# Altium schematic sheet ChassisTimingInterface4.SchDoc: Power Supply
size B; DocumentNumber: 5; Revision: C; SheetNumber: 4; SheetTotal: 12
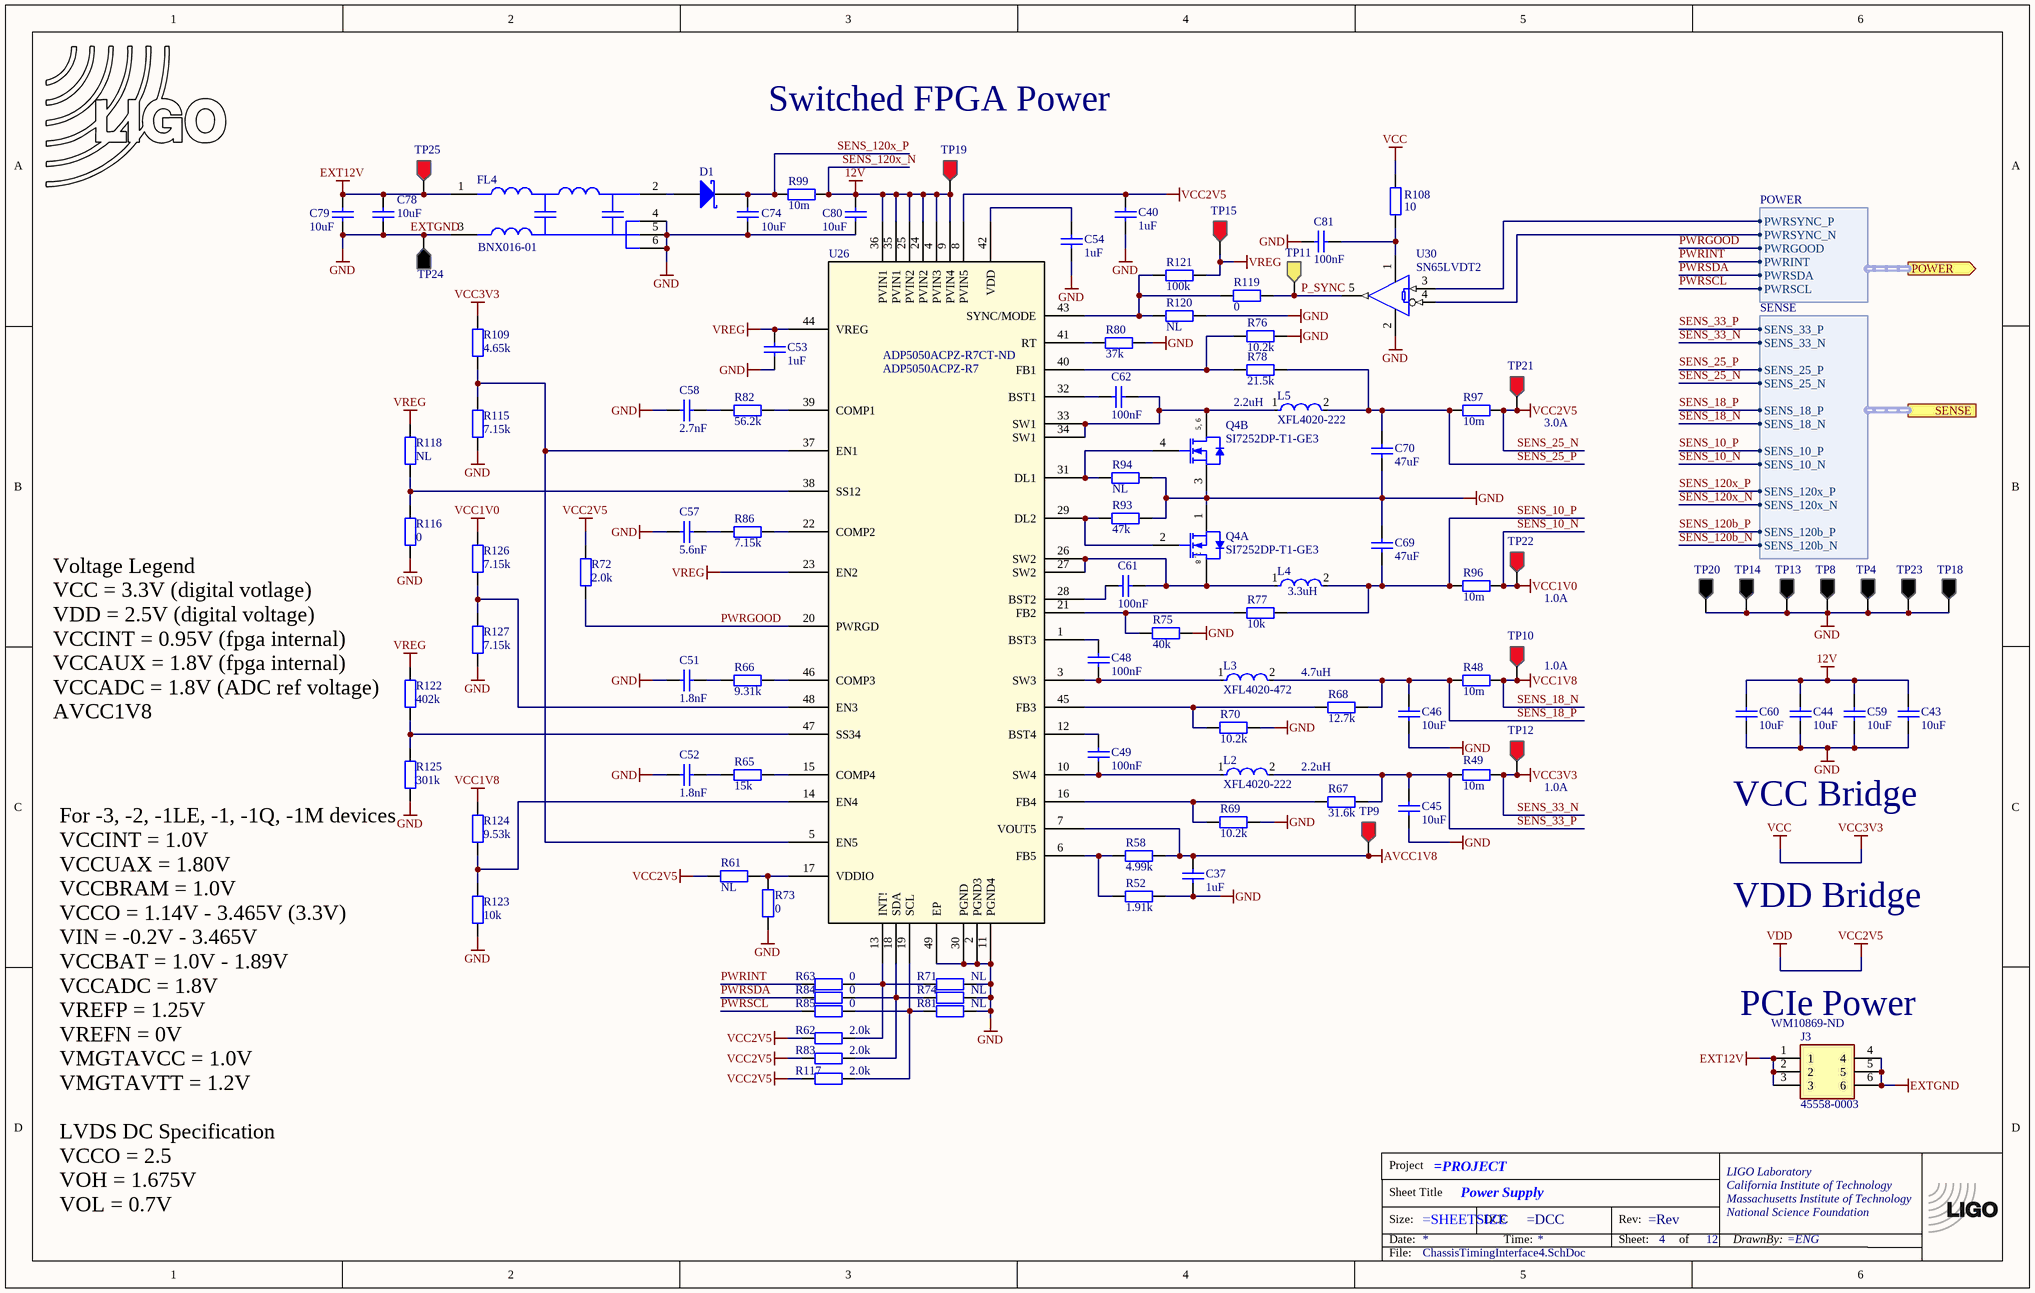
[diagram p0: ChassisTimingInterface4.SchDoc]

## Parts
*  TitleBlock  (value not drawn)  (graphical)
C37  value 1uF  [CC1005-0402]  (hidden comment: 1.0u)
C40  value 1uF  [CC1005-0402]  (hidden comment: 1.0u)
C43  10uF  [CC2013-0805]
C44  10uF  [CC2013-0805]
C45  10uF  [CC2013-0805]
C46  10uF  [CC2013-0805]
C48  100nF  [CC1005-0402]
C49  100nF  [CC1005-0402]
C51  1.8nF  [CC1005-0402]
C52  1.8nF  [CC1005-0402]
C53  value 1uF  [CC1005-0402]  (hidden comment: 1.0u)
C54  value 1uF  [CC1005-0402]  (hidden comment: 1.0u)
C57  5.6nF  [CC1005-0402]
C58  2.7nF  [CC1005-0402]
C59  10uF  [CC2013-0805]
C60  10uF  [CC2013-0805]
C61  100nF  [CC1005-0402]
C62  100nF  [CC1005-0402]
C69  47uF  [CC3216-1206]
C70  47uF  [CC3216-1206]
C74  10uF  [CC2013-0805]
C78  10uF  [CC2013-0805]
C79  10uF  [CC2013-0805]
C80  10uF  [CC2013-0805]
C81  100nF  [CC1005-0402]
D1  LSM115JE3/TR13  [MCSM-DO-214BA-2_L]  (value not drawn)
FL4  BNX016-01  [MURA-BNX016-01_V]
J3  45558-0003  Supplier Part Number 1: WM10869-ND  [455580003]
L2  XFL4020-222  [FP-XAL40-MFG]
L3  XFL4020-472  [FP-XAL40-MFG]
L4  XFL4020-332  [FP-XAL40-MFG]  (value not drawn)
L5  XFL4020-222  [FP-XAL40-MFG]
LOGO4  LIGO logo  [LIGO_LOGO]  (value not drawn)  (graphical)
Q4  SI7252DP-T1-GE3  [VISH-POWERPAKSO-8_A_V]  (parts A,B of 2)
R48  10m  [CC3216-1206]
R49  10m  [CC3216-1206]
R52  1.91k  [CR1005-0402]
R58  4.99k  [CR1608-0603]
R61  NL  [CR1005-0402]
R62  2.0k  [CR1005-0402]
R63  0  [CR1005-0402]
R65  15k  [CR1005-0402]
R66  9.31k  [CR1005-0402]
R67  31.6k  [CR1005-0402]
R68  12.7k  [CR1005-0402]
R69  value 10.2k  [CR1005-0402]  (hidden comment: 10k)
R70  value 10.2k  [CR1005-0402]  (hidden comment: 10k)
R71  NL  [CR1005-0402]
R72  2.0k  [CR1005-0402]
R73  0  [CR1005-0402]
R74  NL  [CR1005-0402]
R75  value 40k  [CR1005-0402]  (hidden comment: 40.2k)
R76  value 10.2k  [CR1005-0402]  (hidden comment: 10k)
R77  10k  [CR1005-0402]
R78  21.5k  [CR1005-0402]
R80  value 37k  [CR1005-0402]  (hidden comment: 37.4k)
R81  NL  [CR1005-0402]
R82  56.2k  [CR1005-0402]
R83  2.0k  [CR1005-0402]
R84  0  [CR1005-0402]
R85  0  [CR1005-0402]
R86  7.15k  [CR1005-0402]
R93  47k  [CR1005-0402]
R94  NL  [CR1005-0402]
R96  10m  [CC3216-1206]
R97  10m  [CC3216-1206]
R99  10m  [CC3216-1206]
R108  value 10  [CR1005-0402]  (hidden comment: 10.0)
R109  value 4.65k  [CR1005-0402]  (hidden comment: 4.7k)
R115  7.15k  [CR1005-0402]
R116  0  [CR1005-0402]
R117  2.0k  [CR1005-0402]
R118  NL  [CR1005-0402]
R119  0  [CR1005-0402]
R120  NL  [CR1005-0402]
R121  100k  [CR1005-0402]
R122  402k  [CR1005-0402]
R123  10k  [CR1005-0402]
R124  9.53k  [CR1005-0402]
R125  301k  [CR1005-0402]
R126  7.15k  [CR1005-0402]
R127  7.15k  [CR1005-0402]
TP4  Testpoint  [TP1-BLK]  (value not drawn)
TP8  Testpoint  [TP1-BLK]  (value not drawn)
TP9  Testpoint  [TP1-RED]  (value not drawn)
TP10  Testpoint  [TP1-RED]  (value not drawn)
TP11  Testpoint  [TP1-YLW]  (value not drawn)
TP12  Testpoint  [TP1-RED]  (value not drawn)
TP13  Testpoint  [TP1-BLK]  (value not drawn)
TP14  Testpoint  [TP1-BLK]  (value not drawn)
TP15  Testpoint  [TP1-RED]  (value not drawn)
TP18  Testpoint  [TP1-BLK]  (value not drawn)
TP19  Testpoint  [TP1-RED]  (value not drawn)
TP20  Testpoint  [TP1-BLK]  (value not drawn)
TP21  Testpoint  [TP1-RED]  (value not drawn)
TP22  Testpoint  [TP1-RED]  (value not drawn)
TP23  Testpoint  [TP1-BLK]  (value not drawn)
TP24  Testpoint  [TP1-BLK]  (value not drawn)
TP25  Testpoint  [TP1-RED]  (value not drawn)
U26  ADP5050ACPZ-R7  Supplier Part Number 1: ADP5050ACPZ-R7CT-ND  [CP-48-13_L]
U30  SN65LVDT2  [SO-G5/E2.4]

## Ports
POWER (out, harness POWER), SENSE (harness SENSE)

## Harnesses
POWER: PWRSYNC_N, PWRSYNC_P, PWRGOOD, PWRINT, PWRSDA, PWRSCL
SENSE: SENS_33_P, SENS_33_N, SENS_25_P, SENS_25_N, SENS_18_P, SENS_18_N, SENS_10_P, SENS_10_N, SENS_120x_P, SENS_120x_N, SENS_120b_P, SENS_120b_N

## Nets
AVCC1V8: C37.2 R58.2 TP9.1 U26.7(VOUT5)
EXT12V: C78.1 C79.1 FL4.1(B) J3.1 J3.2 J3.3 TP25.1
EXTGND: C37.1 C40.1 C43.2 C44.2 C45.1 C46.1 C51.1 C52.1 C53.2 C54.1 C57.1 C58.1 C59.2 C60.2 C69.2 C70.1 C74.2 C78.2 C79.2 C80.2 C81.2 FL4.3(PSG) FL4.4(CG) FL4.5(CG) FL4.6(CG) J3.4 J3.5 J3.6 Q4.1(S1) Q4.3(S2) R52.2 R69.2 R70.2 R71.2 R73.1 R74.2 R75.2 R76.2 R80.2 R81.2 R93.2 R94.2 R115.1 R116.1 R120.2 R123.1 R125.1 R127.1 TP4.1 TP8.1 TP13.1 TP14.1 TP18.1 TP20.1 TP23.1 TP24.1 U26.2(PGND3) U26.11(PGND4) U26.30(PGND) U26.49(EP) U30.2(GND)  [also labelled GND]
SENS_10_N: R96.2 R126.2 TP22.1 ; port SENSE.SENS_10_N  [also labelled VCC1V0]
SENS_18_N: R48.2 R124.2 TP10.1 ; port SENSE.SENS_18_N  [also labelled VCC1V8]
SENS_25_N: C40.2 R61.2 R62.1 R72.2 R83.1 R97.2 R117.1 TP21.1 U26.8(PVIN5) ; port SENSE.SENS_25_N  [also labelled VCC2V5, VDD]
SENS_33_N: R49.2 R108.2 R109.2 TP12.1 ; port SENSE.SENS_33_N  [also labelled VCC, VCC3V3]
SENS_120x_N: C43.1 C44.1 C59.1 C60.1 C80.1 R99.2 TP19.1 U26.4(PVIN3) U26.9(PVIN4) U26.24(PVIN2) U26.25(PVIN2) U26.35(PVIN1) U26.36(PVIN1) ; port SENSE.SENS_120x_N  [also labelled 12V]
VREG: C53.1 R118.2 R121.2 R122.2 TP15.1 U26.23(EN2) U26.44(VREG)
P_SYNC: R119.2 TP11.1 U30.5(R)
PWRGOOD: R72.1 U26.20(PWRGD) ; port POWER.PWRGOOD
PWRINT: R63.1 ; port POWER.PWRINT
PWRSCL: R85.1 ; port POWER.PWRSCL
PWRSDA: R84.1 ; port POWER.PWRSDA
SENS_10_P: C69.1 L4.2 R77.2 R96.1 ; port SENSE.SENS_10_P
SENS_18_P: C46.2 L3.2 R48.1 R68.2 ; port SENSE.SENS_18_P
SENS_25_P: C70.2 L5.2 R78.2 R97.1 ; port SENSE.SENS_25_P
SENS_33_P: C45.2 L2.2 R49.1 R67.2 ; port SENSE.SENS_33_P
SENS_120x_P: C74.1 D1.2(K) R99.1 ; port SENSE.SENS_120x_P
NetC48_1: C48.1 L3.1 U26.3(SW3)
NetC48_2: C48.2 U26.1(BST3)
NetC49_1: C49.1 L2.1 U26.10(SW4)
NetC49_2: C49.2 U26.12(BST4)
NetC51_2: C51.2 R66.1
NetC52_2: C52.2 R65.1
NetC54_2: C54.2 U26.42(VDD)
NetC57_2: C57.2 R86.1
NetC58_2: C58.2 R82.1
NetC61_1: C61.1 U26.28(BST2)
NetC61_2: C61.2 L4.1 Q4.7(D1) Q4.8(D1) U26.26(SW2) U26.27(SW2)
NetC62_1: C62.1 U26.32(BST1)
NetC62_2: C62.2 L5.1 Q4.5(D2) Q4.6(D2) U26.33(SW1) U26.34(SW1)
NetC81_1: C81.1 R108.1 U30.1(VCC)
NetD1_1: D1.1(A) FL4.2(CB)
NetQ4_2: Q4.2(G1) R93.1 U26.29(DL2)
NetQ4_4: Q4.4(G2) R94.1 U26.31(DL1)
NetR52_1: R52.1 R58.1 U26.6(FB5)
NetR61_1: R61.1 R73.2 U26.17(VDDIO)
NetR62_2: R62.2 R63.2 R71.1 U26.13(INT!)
NetR65_2: R65.2 U26.15(COMP4)
NetR66_2: R66.2 U26.46(COMP3)
NetR67_1: R67.1 R69.1 U26.16(FB4)
NetR68_1: R68.1 R70.1 U26.45(FB3)
NetR74_1: R74.1 R83.2 R84.2 U26.18(SDA)
NetR75_1: R75.1 R77.1 U26.21(FB2)
NetR76_1: R76.1 R78.1 U26.40(FB1)
NetR80_1: R80.1 U26.41(RT)
NetR81_1: R81.1 R85.2 R117.2 U26.19(SCL)
NetR82_2: R82.2 U26.39(COMP1)
NetR86_2: R86.2 U26.22(COMP2)
NetR109_1: R109.1 R115.2 U26.5(EN5) U26.37(EN1)
NetR116_2: R116.2 R118.1 U26.38(SS12)
NetR119_1: R119.1 R120.1 R121.1 U26.43(SYNC/MODE)
NetR122_1: R122.1 R125.2 U26.47(SS34)
NetR123_2: R123.2 R124.1 U26.14(EN4)
NetR126_1: R126.1 R127.2 U26.48(EN3)
NetU30_3: U30.3(A) ; port POWER.PWRSYNC_P
NetU30_4: U30.4(B) ; port POWER.PWRSYNC_N

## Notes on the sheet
- Switched FPGA Power
- 2.2uH
- 3.0A
- (near L4) 3.3uH
- 1.0A
- 4.7uH
- (near TP10) 1.0A
- Voltage Legend
  VCC = 3.3V (digital votlage)
  VDD = 2.5V (digital voltage)
  VCCINT = 0.95V (fpga internal)
  VCCAUX = 1.8V (fpga internal)
  VCCADC = 1.8V (ADC ref voltage)
  AVCC1V8
- VCC Bridge
- VDD Bridge
- (near J3) PCIe Power
- (near R125) For -3, -2, -1LE, -1, -1Q, -1M devices
  VCCINT = 1.0V
  VCCUAX = 1.80V
  VCCBRAM = 1.0V
  VCCO = 1.14V - 3.465V (3.3V)
  VIN = -0.2V - 3.465V
  VCCBAT = 1.0V - 1.89V
  VCCADC = 1.8V
  VREFP = 1.25V
  VREFN = 0V
  VMGTAVCC = 1.0V
  VMGTAVTT = 1.2V
  LVDS DC Specification
  VCCO = 2.5
  VOH = 1.675V
  VOL = 0.7V

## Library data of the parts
C37 C40 C53 C54 = ChipCap: C0402 1.0uF; Part Number: 490-10017-1-ND; Tolerance: 10%
C43-C46 C59 C60 C74 C78-C80 = ChipCap: C0805 10uF; Part Number: 1276-6454-1-ND; Tolerance: 10%
C48 C49 C61 C62 C81 = ChipCap: C0402 0.1uF; Part Number: 1276-6720-1-ND; Tolerance: 10%
C51 C52 = ChipCap: C0402 1.8nF; Part Number: 399-17370-1-ND; Tolerance: 10%
C57 = ChipCap: C0402 5.6nF; Part Number: 1276-1578-1-ND; Tolerance: 10%
C58 = ChipCap: C0402 2.7nF; Part Number: 399-14439-1-ND; Tolerance: 10%
C69 C70 = ChipCap: C1206 47uF; Part Number: 490-16268-1-ND; Tolerance: 10%
D1 = CMP-2000-06604-1: Ultra Low Forward Voltage Schottky Rectifier, 15 V, -55 to 100 degC, 2-Pin Molded, RoHS, Tape and Reel; Part Number: LSM115JE3/TR13CT-ND
FL4 = CMP-2000-05960-1: Block Type EMIFIL(R) Reference Specification, 15 A, 25 V, -40 to 125 degC, 6-Pin THD, RoHS, Bulk; Part Number: 490-5055-ND
J3 = 45558-0003: Connector
L2 L5 = CMP-11268-000008-1: INDUCTOR, 2.2uH; Value: 10uH; Tolerance: 20%
L3 = CMP-11268-000008-1: INDUCTOR, 4.7uH; Value: 10uH; Tolerance: 20%
L4 = CMP-11268-000008-1: INDUCTOR, 3.3uH; Value: 10uH; Tolerance: 20%
LOGO4 = LIGO_logo
Q4 = CMP-2000-07602-1: Dual N-Channel (D-S) MOSFET, 100 V, 36.7 A, -55 to 150 degC, 8-Pin SMD, RoHS, Tape and Reel; Part Number: SI7252DP-T1-GE3CT-ND
R48 R49 R96 R97 R99 = ChipRes1: R1206 10m; Part Number: 273-PCS1206DR0100ETCT-ND; Tolerance: 0.1%
R52 = ChipRes1: R0402 1.91k; Part Number: YAG4201CT-ND; Tolerance: 0.1%
R58 = ChipRes1: R0603 4.99k; Part Number: RR08P4.99KDCT-ND; Tolerance: 0.1%
R61 R71 R74 R81 R94 R118 R120 = ChipRes1: Resistor, surface mount; Tolerance: 0.1%
R62 R72 R83 R117 = ChipRes1: R0402 2.0k; Part Number: RG10P2.00KDCT-ND; Tolerance: 0.1%
R63 R73 R84 R85 R116 R119 = ChipRes1: R0402 0; Part Number: 541-2877-1-ND; Tolerance: 0.1%
R65 = ChipRes1: R0402 15k; Part Number: RR05P15.0KDCT-ND; Tolerance: 0.1%
R66 = ChipRes1: R0402 9.31k; Part Number: 311-2336-1-ND; Tolerance: 0.1%
R67 = ChipRes1: R0402 31.6k; Part Number: 311-2272-1-ND; Tolerance: 0.1%
R68 = ChipRes1: R0402 12.7k; Part Number: RNCF0402DTE12K7CT-ND; Tolerance: 0.1%
R69 R70 R76 R77 R123 = ChipRes1: R0402 10k; Part Number: RR05P10.0KDCT-ND; Tolerance: 0.1%
R75 = ChipRes1: R0402 40.2k; Part Number: P18270CT-ND; Tolerance: 0.1%
R78 = ChipRes1: R0402 21.5K; Part Number: RNCF0402DTE21K5CT-ND; Tolerance: 0.1%
R80 = ChipRes1: R0402 37.4k; Part Number: YAG4250CT-ND; Tolerance: 0.1%
R82 = ChipRes1: R0402 56.2k; Part Number: 311-2303-1-ND; Tolerance: 0.1%
R86 R115 R126 R127 = ChipRes1: R0402 7.15k; Part Number: YAG1478CT-ND; Tolerance: 0.1%
R93 = ChipRes1: R0402 47k; Part Number: RG10P47KBCT-ND; Tolerance: 0.1%
R108 = ChipRes1: R0402 10; Part Number: A127127CT-ND; Tolerance: 0.1%
R109 = ChipRes1: R0402 4.7k; Part Number: RR05P4.7KDCT-ND; Tolerance: 0.1%
R121 = ChipRes1: R0402 100k; Part Number: RR05P100KDCT-ND; Tolerance: 0.1%
R122 = ChipRes1: R0402 402k; Part Number: RMCF0402FT402KCT-ND; Tolerance: 0.1%
R124 = ChipRes1: R0402 9.31k; Part Number: YAG4326CT-ND; Tolerance: 0.1%
R125 = ChipRes1: R0402 301k; Part Number: RMCF0402FT301KCT-ND; Tolerance: 0.1%
TP4 TP8 TP13 TP14 TP18 TP20 TP23 TP24 = TP_GND: Testpoint, black; Part Number: 36-5001-ND
TP9 TP10 TP12 TP15 TP19 TP21 TP22 TP25 = TP_POSITIVE: Testpoint, red; Part Number: 36-5000-ND
TP11 = TP_SIGNAL: Testpoint, yellow; Part Number: 36-5004-ND
U26 = ADP5050ACPZ-R7: Artix 7 Power Supply
U30 = SN65LVDT2DBV: Single LVDS Receiver with 100 Ohm termination; Part Number: 296-6896-1-ND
